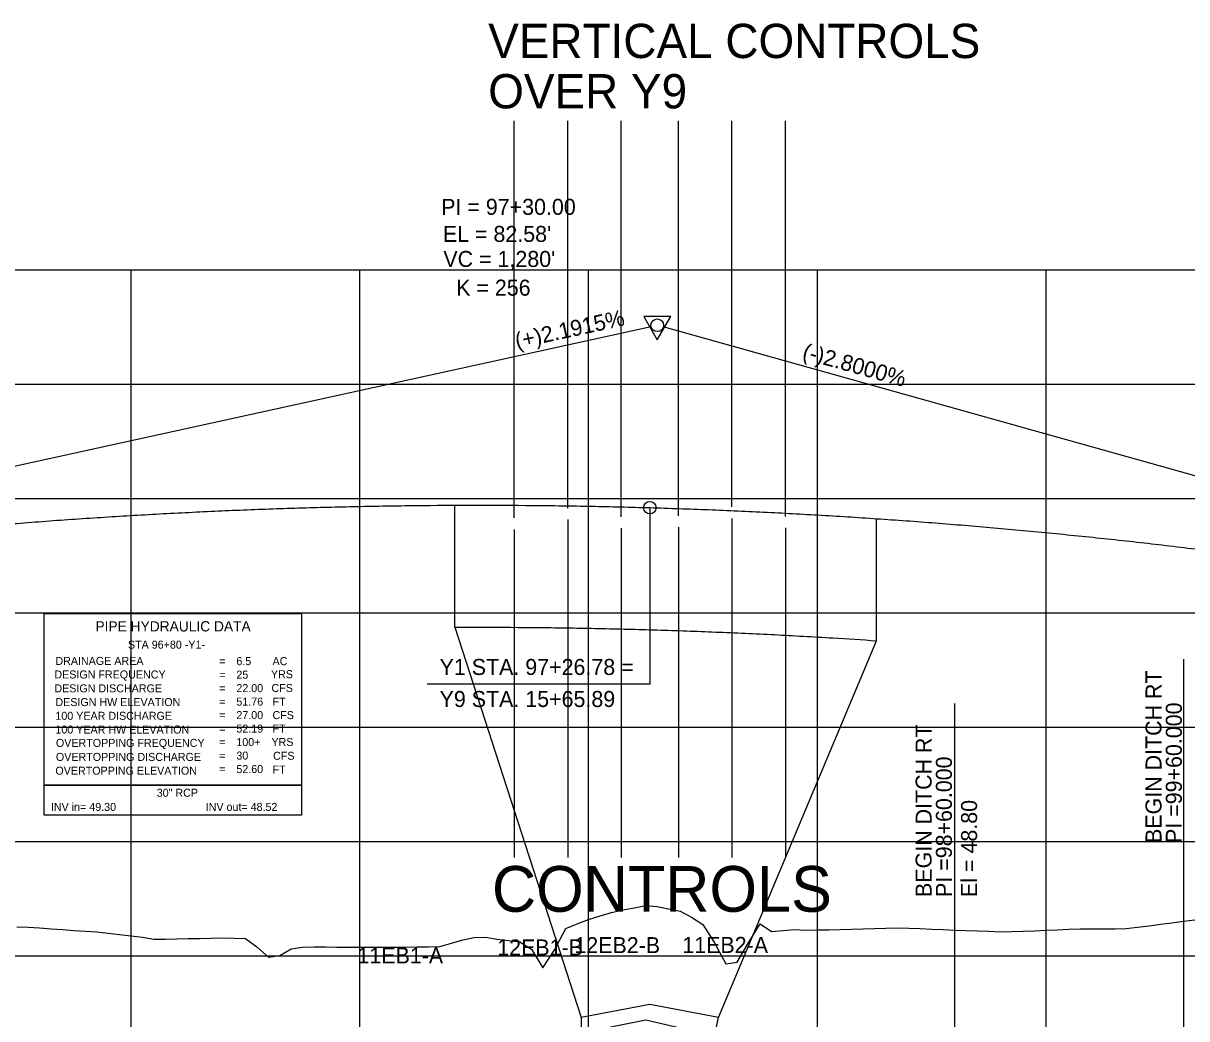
# Model space of a CAD drawing. Extents: x 2345490 to 2436403, y 465165 to 573888.
# Drawn here: x 2389774 to 2390283, y 558007 to 558442 of the extents above; entities that cross this region are included whole.
import ezdxf

# ---------------------------------------------------------------- set-up
doc = ezdxf.new("R2010")
doc.units = 0
for name, color, linetype in [('Old_Level_2', 7, 'Continuous'), ('Old_Level_3', 7, 'Continuous'), ('Old_Level_4', 7, 'Continuous'), ('Old_Level_57', 7, 'Continuous'), ('Old_Level_6', 7, 'Continuous'), ('Old_Level_62', 7, 'Continuous'), ('Old_Level_63', 7, 'Continuous'), ('Prop Road Sect_ Boring - Header Labels from Geopak', 7, 'Continuous')]:
    doc.layers.add(name, color=color, linetype=linetype)

msp = doc.modelspace()

# ---------------------------------------------------------------- linework, layer by layer
at = {"layer": 'Old_Level_2'}
for p, q in [((2389411.5425, 558169.65525), (2390048.8565, 558309.32425)), ((2390691.5425, 558130.713), (2390054.19075, 558309.1715))]:
    msp.add_line(p, q, dxfattribs=at)
msp.add_lwpolyline([(2390057.42075, 558313.69725), (2390045.67825, 558313.68275), (2390051.56175, 558303.5645)], close=True, dxfattribs=at)
for centre in [(2390051.5425, 558309.913), (2390048.3225, 558230.143)]:
    msp.add_circle(centre, 2.75, dxfattribs=at)
msp.add_spline([(2389411.5425, 558169.65525), (2389437.1425, 558175.13775), (2389462.7425, 558180.36475), (2389488.3425, 558185.336), (2389513.9425, 558190.052), (2389539.5425, 558194.51225), (2389565.1425, 558198.717), (2389590.7425, 558202.666), (2389616.3425, 558206.3595), (2389641.9425, 558209.7975), (2389667.5425, 558212.98), (2389693.1425, 558215.90675), (2389718.7425, 558218.57825), (2389744.3425, 558220.994), (2389769.9425, 558223.154), (2389795.5425, 558225.05875), (2389821.1425, 558226.70775), (2389846.7425, 558228.10125), (2389872.3425, 558229.239), (2389897.9425, 558230.12125), (2389923.5425, 558230.74825), (2389949.1425, 558231.11925), (2389974.7425, 558231.235), (2390000.3425, 558231.095), (2390025.9425, 558230.6995), (2390051.5425, 558230.0485), (2390077.1425, 558229.14175), (2390102.7425, 558227.97975), (2390128.3425, 558226.562), (2390153.9425, 558224.8885), (2390179.5425, 558222.95975), (2390205.1425, 558220.77525), (2390230.7425, 558218.33525), (2390256.3425, 558215.6395), (2390281.9425, 558212.6885), (2390307.5425, 558209.48175), (2390333.1425, 558206.0195), (2390358.7425, 558202.3015), (2390384.3425, 558198.328), (2390409.9425, 558194.09925), (2390435.5425, 558189.6145), (2390461.1425, 558184.8745), (2390486.7425, 558179.87875), (2390512.3425, 558174.6275), (2390537.94275, 558169.12075), (2390563.54275, 558163.35825), (2390589.14275, 558157.34025), (2390614.74275, 558151.06675), (2390640.34275, 558144.53775), (2390665.94275, 558137.753), (2390691.54275, 558130.713)], degree=3, dxfattribs=at)
at = {"layer": 'Old_Level_3'}
for p, q in [((2390048.3225, 558230.143), (2390048.3225, 558152.99675)), ((2390281.5425, 558163.89647), (2390281.5425, 557985.113)), ((2390048.3225, 558152.99675), (2389950.96725, 558152.99675)), ((2390181.5425, 558144.5335), (2390181.5425, 557972.113))]:
    msp.add_line(p, q, dxfattribs=at)
at = {"layer": 'Old_Level_4'}
for p, q in [((2389783.55325, 558183.8278), (2389896.05325, 558183.8278)), ((2389783.55325, 558108.8278), (2389783.55325, 558183.8278)), ((2389896.05325, 558183.8278), (2389896.05325, 558108.8278)), ((2389896.05325, 558108.8278), (2389783.55325, 558108.8278))]:
    msp.add_line(p, q, dxfattribs=at)
msp.add_lwpolyline([(2389783.55325, 558108.8278), (2389896.05325, 558108.8278), (2389896.05325, 558095.6128), (2389783.55325, 558095.6128)], close=True, dxfattribs=at)
at = {"layer": 'Old_Level_57'}
for p, q in [((2381271.54275, 558334.11325), (2393041.55275, 558334.11325)), ((2389821.54225, 557784.21325), (2389821.54225, 558334.21325)), ((2389821.54225, 557784.11325), (2389821.54225, 558334.11325)), ((2389921.54225, 557784.21325), (2389921.54225, 558334.21325)), ((2389921.54225, 557784.11325), (2389921.54225, 558334.11325)), ((2390021.54225, 557784.21325), (2390021.54225, 558334.21325)), ((2390021.54225, 557784.11325), (2390021.54225, 558334.11325)), ((2390121.54225, 557784.21325), (2390121.54225, 558334.21325)), ((2390121.54225, 557784.11325), (2390121.54225, 558334.11325)), ((2390221.54225, 557784.21325), (2390221.54225, 558334.21325)), ((2390221.54225, 557784.11325), (2390221.54225, 558334.11325)), ((2381271.54275, 558284.11325), (2393041.55275, 558284.11325)), ((2381271.54275, 558234.11325), (2393041.55275, 558234.11325)), ((2381271.54275, 558184.11325), (2393041.55275, 558184.11325)), ((2381271.54275, 558134.11325), (2393041.55275, 558134.11325)), ((2381271.54275, 558084.11325), (2393041.55275, 558084.11325)), ((2381271.5425, 558034.11325), (2393041.55275, 558034.11325))]:
    msp.add_line(p, q, dxfattribs=at)
at = {"layer": 'Old_Level_6'}
for p, q in [((2389963.1225, 558177.84425), (2389963.1225, 558231.1035)), ((2390147.3725, 558171.972), (2390147.3725, 558225.33075)), ((2389963.1225, 558177.84425), (2390018.34475, 558007.19575)), ((2390078.30025, 558007.19575), (2390147.3725, 558171.972)), ((2390048.3225, 558012.813), (2390018.34475, 558007.19575)), ((2390078.30025, 558007.19575), (2390048.3225, 558012.813))]:
    msp.add_line(p, q, dxfattribs=at)
msp.add_lwpolyline([(2390018.34475, 558007.19575), (2390018.34475, 558000.47425), (2390046.5425, 558006.1185), (2390076.5775, 557999.13), (2390078.30025, 558007.19575), (2390048.3225, 558012.813)], close=True, dxfattribs=at)
msp.add_spline([(2389963.1225, 558177.8445), (2389974.7425, 558177.8655), (2390000.3425, 558177.7255), (2390025.9425, 558177.33), (2390051.5425, 558176.679), (2390077.1425, 558175.77225), (2390102.7425, 558174.61025), (2390128.3425, 558173.1925), (2390147.3725, 558171.97275)], degree=3, dxfattribs=at)
at = {"layer": 'Old_Level_62'}
for points in [[(2389821.5425, 558042.93275), (2389826.5425, 558042.31725), (2389831.5425, 558041.4205), (2389836.5425, 558041.442), (2389841.5425, 558041.567), (2389846.5425, 558041.692), (2389851.5425, 558041.817), (2389856.5425, 558041.94175), (2389861.5425, 558042.06675), (2389866.5425, 558041.94575), (2389871.5425, 558041.816), (2389876.5425, 558038.08275), (2389881.5425, 558033.59125), (2389886.5425, 558034.2915), (2389891.5425, 558037.16025), (2389896.5425, 558038.0155), (2389901.5425, 558038.04275), (2389906.5425, 558038.0605), (2389911.5425, 558038.01025), (2389916.5425, 558037.95375), (2389921.5425, 558037.939), (2389926.5425, 558037.9355), (2389931.5425, 558037.9505), (2389936.5425, 558037.97675), (2389941.5425, 558038.003), (2389946.5425, 558038.06075), (2389951.5425, 558038.12125), (2389956.5425, 558038.182), (2389961.5425, 558039.65025), (2389966.5425, 558041.2005), (2389971.5425, 558042.2015), (2389976.5425, 558042.2555), (2389981.5425, 558041.42775), (2389986.5425, 558040.85375), (2389991.5425, 558040.283), (2389996.5425, 558037.04725), (2390001.5425, 558028.92525), (2390006.5425, 558036.5105), (2390011.5425, 558046.145), (2390016.5425, 558048.1595), (2390021.5425, 558050.06325), (2390026.5425, 558051.71825), (2390031.5425, 558053.17275), (2390036.5425, 558054.28925), (2390041.5425, 558055.18475), (2390046.5425, 558056.1245), (2390051.5425, 558055.67925), (2390056.5425, 558054.67575), (2390061.5425, 558053.68075), (2390066.5425, 558051.0015), (2390071.5425, 558047.8145), (2390076.5425, 558039.80225), (2390081.5425, 558030.6195), (2390086.5425, 558031.42675), (2390091.5425, 558040.20475), (2390096.5425, 558048.1995), (2390101.5425, 558044.8765), (2390106.5425, 558045.24025), (2390111.5425, 558045.66075), (2390116.5425, 558045.367), (2390121.5425, 558045.46525), (2390126.5425, 558045.5635), (2390131.5425, 558045.68225), (2390136.5425, 558045.84), (2390141.5425, 558045.9975), (2390146.5425, 558046.15525), (2390151.5425, 558046.31275), (2390156.5425, 558046.47025), (2390161.5425, 558046.27875), (2390166.5425, 558046.09475), (2390171.5425, 558045.86425), (2390176.5425, 558045.63525), (2390181.5425, 558045.406), (2390186.5425, 558045.2275), (2390191.5425, 558045.05425), (2390196.5425, 558044.881), (2390201.5425, 558044.70775), (2390206.5425, 558044.739), (2390211.5425, 558044.94625), (2390216.5425, 558045.1535), (2390221.5425, 558045.36075), (2390226.5425, 558045.568), (2390231.5425, 558045.77525), (2390236.5425, 558045.9115), (2390241.5425, 558045.94225), (2390246.5425, 558045.973), (2390251.5425, 558046.00775), (2390256.5425, 558046.0845), (2390261.5425, 558046.672), (2390266.5425, 558047.32175), (2390271.5425, 558047.9715), (2390276.5425, 558048.6215), (2390281.5425, 558049.27125), (2390286.5425, 558049.921)], [(2389771.5425, 558046.774), (2389776.5425, 558046.66275), (2389781.5425, 558046.396), (2389786.5425, 558046.03525), (2389791.5425, 558045.6745), (2389796.5425, 558045.31375), (2389801.5425, 558044.953), (2389806.5425, 558044.59225), (2389811.5425, 558044.04275), (2389816.5425, 558043.48775), (2389821.5425, 558042.93275)]]:
    msp.add_lwpolyline(points, dxfattribs=at)
at = {"layer": 'Old_Level_63'}
for p, q in [((2389989.0325, 558225.633), (2389989.0325, 558399.3225)), ((2390012.4525, 558229.913), (2390012.4525, 558399.3225)), ((2390035.8425, 558226.153), (2390035.8425, 558399.3225)), ((2390060.7725, 558226.603), (2390060.7725, 558399.3225)), ((2390084.1925, 558230.463), (2390084.1925, 558399.3225)), ((2390107.5825, 558226.283), (2390107.5825, 558399.3225)), ((2390012.4525, 558224.913), (2390012.4525, 558077.0925)), ((2390035.8425, 558221.153), (2390035.8425, 558077.0925)), ((2390060.7725, 558221.603), (2390060.7725, 558077.0925)), ((2390084.1925, 558225.463), (2390084.1925, 558077.0925)), ((2390107.5825, 558221.283), (2390107.5825, 558077.0925)), ((2389989.0325, 558220.633), (2389989.0325, 558077.0925))]:
    msp.add_line(p, q, dxfattribs=at)

# ---------------------------------------------------------------- texts
at = {"layer": 'Old_Level_2'}
for s, height, p in [('PI = 97+30.00', 7.0000005, (2389957.105, 558358.1885)), ("EL = 82.58'", 7.0000005, (2389957.83675, 558346.34575)), ("VC = 1,280'", 7.0000005, (2389958.057, 558335.4065)), ('K = 256', 7.000001, (2389963.6625, 558322.8505))]:
    msp.add_text(s, height=height, dxfattribs=at).set_placement(p)
for s, rotation, p in [('(+)2.1915%', 12.3610972, (2389990.24175, 558299.5495)), ('(-)2.8000%', 344.3577528, (2390114.571, 558295.39725))]:
    msp.add_text(s, height=7.000001, rotation=rotation, dxfattribs=at).set_placement(p)
at = {"layer": 'Old_Level_3'}
for s, p in [('Y1 STA. 97+26.78 = ', (2389956.41025, 558156.9805)), ('Y9 STA. 15+65.89', (2389956.41025, 558142.98025))]:
    msp.add_text(s, height=7.0000005, dxfattribs=at).set_placement(p)
for s, height, p in [('BEGIN DITCH RT', 7.0000005, (2390271.9906, 558083.53113)), ('PI =99+60.000', 7.0000005, (2390280.8645, 558083.53113)), ('BEGIN DITCH RT', 7.0000005, (2390171.4906, 558059.91273)), ('PI =98+60.000', 7.0000005, (2390180.3645, 558059.91273)), ('El = 48.80', 7.000001, (2390191.3645, 558059.91273))]:
    msp.add_text(s, height=height, rotation=90, dxfattribs=at).set_placement(p)
at = {"layer": 'Old_Level_4'}
for s, height, p in [('PIPE HYDRAULIC DATA', 4.49985, (2389805.95325, 558176.0028)), ('STA 96+80 -Y1-', 3.4998, (2389820.174, 558168.5023)), ('DRAINAGE AREA', 3.49995, (2389788.45325, 558161.3778)), ('=        ', 3.49995, (2389860.10325, 558161.2778)), ('6.5', 3.49995, (2389867.56375, 558161.2773)), ('AC', 3.49995, (2389883.37825, 558161.2778)), ('DESIGN FREQUENCY', 3.49995, (2389788.00325, 558155.4528)), ('=        ', 3.49995, (2389860.10325, 558155.3778)), ('25', 3.49995, (2389867.56375, 558155.3773)), ('YRS', 3.49995, (2389882.67825, 558155.5778)), ('DESIGN DISCHARGE', 3.49995, (2389788.00325, 558149.3778)), ('=        ', 3.49995, (2389860.10325, 558149.4778)), ('22.00', 3.49995, (2389867.56375, 558149.4773)), ('CFS', 3.49995, (2389882.90325, 558149.5528)), ('DESIGN HW ELEVATION', 3.49995, (2389788.45325, 558143.3778)), ('=        ', 3.49995, (2389860.10325, 558143.5778)), ('51.76', 3.49995, (2389867.56375, 558143.5773)), ('FT', 3.49995, (2389883.37825, 558143.5778)), ('100 YEAR DISCHARGE', 3.49995, (2389788.45325, 558137.3778)), ('=        ', 3.49995, (2389860.10325, 558137.6778)), ('27.00', 3.49995, (2389867.56375, 558137.6773)), ('CFS', 3.49995, (2389883.37825, 558137.6778)), ('100 YEAR HW ELEVATION', 3.49995, (2389788.45325, 558131.3778)), ('52.19', 3.49995, (2389867.56375, 558131.77755)), ('FT', 3.49995, (2389883.37825, 558131.7778)), ('=        ', 3.49995, (2389860.10325, 558131.7778)), ('100+', 3.49995, (2389867.56375, 558125.87755)), ('YRS', 3.49995, (2389882.90325, 558125.9278)), ('OVERTOPPING FREQUENCY', 3.49995, (2389788.67825, 558125.5278)), ('=        ', 3.49995, (2389860.10325, 558125.8778)), ('OVERTOPPING DISCHARGE', 3.49995, (2389788.67825, 558119.4028)), ('=        ', 3.49995, (2389860.10325, 558119.9778)), ('30', 3.49995, (2389867.56375, 558119.97755)), ('CFS', 3.49995, (2389883.60325, 558119.9028)), ('OVERTOPPING ELEVATION', 3.49995, (2389788.45325, 558113.3778)), ('=        ', 3.49995, (2389860.10325, 558114.0778)), ('52.60', 3.49995, (2389867.56375, 558114.07755)), ('FT', 3.49995, (2389883.37825, 558113.8778)), ('30" RCP', 3.4998, (2389832.759, 558103.72555)), ('INV in= 49.30', 3.4998, (2389786.48575, 558097.5398)), ('INV out= 48.52', 3.4998, (2389854.1625, 558097.5398))]:
    msp.add_text(s, height=height, dxfattribs=at).set_placement(p)
at = {"layer": 'Old_Level_63'}
for s, height, p in [('VERTICAL CONTROLS', 15, (2389977.66325, 558426.7435)), ('OVER Y9 ', 15, (2389977.66325, 558404.7435)), ('CONTROLS', 20, (2389979.292, 558053.433))]:
    msp.add_text(s, height=height, dxfattribs=at).set_placement(p)
at = {"layer": 'Prop Road Sect_ Boring - Header Labels from Geopak'}
for s, p in [('11EB1-A', (2389920.49526, 558030.814)), ('12EB1-B', (2389981.62124, 558034.35303)), ('12EB2-B', (2390015.32299, 558035.33938)), ('11EB2-A', (2390062.511, 558035.42666))]:
    msp.add_text(s, height=7, dxfattribs=at).set_placement(p)

doc.saveas('drawing.dxf')
